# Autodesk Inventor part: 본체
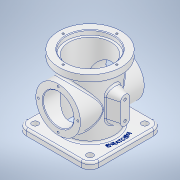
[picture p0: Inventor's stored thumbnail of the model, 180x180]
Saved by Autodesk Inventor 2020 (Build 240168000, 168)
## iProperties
Created: 2021-03
Part Number: 본체
Material: 알루미늄 6061
Document SubType Name: Modeling
Designer: USER
Mass: 869.331 g
Surface Area: 881.277 cm^2
Volume: 321.975 cm^3
Density: 2.7 g/cm^3
Appearance: 알루미늄 - 평지
Author: USER
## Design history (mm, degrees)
sketch "스케치1"
  geometry: L1 (-57, 57)-(57, 57); L2 (57, 57)-(57, -57); L3 (57, -57)-(-57, -57); L4 (-57, -57)-(-57, 57); L5 (-57, 57)-(57, -57); L6 (57, 57)-(-57, -57); 1 further point
  constraints: 12 end point, 2 midpoint, 2 parallel, 2 perpendicular, 1 horizontal
  dimensions: "d0" = 114 distance of L2.end L3.end
extrude "돌출1" new body sketch "스케치1" distance "d1" = 10; taper "d2" = 0 deg
sketch "스케치2"
  geometry: C1 r 38 at (0, 0); 1 further point
  constraints: 1 centre point, 1 coincident
  dimensions: "d3" = 76 diameter of C1
extrude "돌출2" join sketch "스케치2" distance "d4" = 88; taper "d5" = 0 deg
sketch "스케치3"
  geometry: C1 r 49 at (0, 0); 1 further point
  constraints: 1 centre point, 1 coincident
  dimensions: "d6" = 98 diameter of C1
extrude "돌출3" join sketch "스케치3" distance "d7" = 13; taper "d8" = 0 deg
sketch "스케치4"
  geometry: L1 (57, 0)-(-57, 0) reference; C1 r 35 at (0, 54); 1 further point
  constraints: 1 centre point, 1 vertical alignment
  dimensions: "d9" = 70 diameter of C1; "d10" = 54 distance from line of L1 C1.centre
extrude "돌출4" join sketch "스케치4" stored distance "d11" = 100; taper "d12" = 0 deg
sketch "스케치5"
  geometry: C1 r 37 at (0, 0); 1 further point
  constraints: 1 centre point, 1 coincident
  dimensions: "d13" = 74 diameter of C1
extrude "돌출5" cut sketch "스케치5" distance "d14" = 7; taper "d15" = 0 deg
sketch "스케치6"
  geometry: C1 r 33 at (0, 0); 1 further point
  constraints: 1 centre point, 1 coincident
  dimensions: "d16" = 66 diameter of C1
extrude "돌출6" cut sketch "스케치6" extent not by distance; stored distance "d17" = 7; taper "d18" = 0 deg
sketch "스케치8"
  geometry: C1 r 35 at (0, 0) reference; C2 r 24 at (0, 0); 1 further point
  constraints: 1 centre point, 1 coincident
  dimensions: "d19" = 48 diameter of C2
extrude "돌출7" cut sketch "스케치8" extent not by distance; stored distance "d20" = 0; taper "d21" = 0 deg
sketch "스케치9"
  geometry: L1 (24, 22.65)-(24, 50) reference; C1 r 37 at (0, 0) reference; C2 r 49 at (0, 0) reference; 2 further points
  constraints: 1 vertical alignment
  dimensions: "d22" = 42 distance of point (0, 0) point (0, 42)
hole "구멍1" sketch "스케치9" at (0, 42) diameter "d23" = 3.242; stored, may be unused: countersink angle "d27" = 90 deg, drill point angle "d29" = 118 deg; dims "d24" = 6, "d25" = 4, "d26" = 2, "d28" = 8
sketch "스케치10"
  geometry: C1 r 24 at (0, 0) reference; C2 r 35 at (0, 0) reference; 2 further points
  constraints: 1 vertical alignment
  dimensions: "d33" = 31 distance of C1.centre point (0, 31)
hole "구멍2" sketch "스케치10" at (0, 31) diameter "d34" = 3.242; stored, may be unused: countersink angle "d38" = 90 deg, drill point angle "d40" = 118 deg; dims "d35" = 6, "d36" = 4, "d37" = 2, "d39" = 8
node "작업 평면1"
sketch "스케치11"
  geometry: L1 (70, 0)-(41, 0); L2 (70, 7)-(41, 7); L3 (41, -7)-(70, -7); L4 (0, 57)-(0, -57) reference; A1 r 7 centre (70, 0) between (70, -7) and (70, 7); A2 r 7 centre (41, 0) between (41, 7) and (41, -7); 3 further points
  constraints: 8 end point, 4 point on circle, 4 tangent, 2 centre point, 2 midpoint, 1 horizontal, 1 horizontal alignment, 1 parallel
  dimensions: "d45" = 14 distance between parallel lines of L3 L2; "d85" = 41 distance from line of L4 L1.end; "d87" = 29 distance of L1.start L1.end
extrude "돌출8" join sketch "스케치11" stored distance "d48" = 7; taper "d49" = 15 deg
sketch "스케치12"
  geometry: L1 (57, 57)-(-57, 57) reference; L2 (57, -57)-(57, 57) reference; C1 r 5 at (43, 43); 1 further point
  constraints: 1 centre point
  dimensions: "d50" = 10 diameter of C1; "d51" = 14 distance from line of L1 C1.centre; "d52" = 14 distance from line of L2 C1.centre
extrude "돌출9" cut sketch "스케치12" extent not by distance; stored distance "d53" = 0; taper "d54" = 0 deg
fillet "모깎기1" dims "d55" = 14
fillet "모깎기2" dims "d56" = 3
fillet "모깎기3" dims "d57" = 3
fillet "모깎기4" dims "d58" = 3
fillet "모깎기5" dims "d59" = 3
fillet "모깎기6" dims "d60" = 3
fillet "모깎기7" dims "d61" = 3
chamfer "모따기1" distance "d62" = 1; stored, may be unused: second distance "d63" = 2, angle "d64" = 45 deg
chamfer "모따기2" distance "d65" = 1; stored, may be unused: second distance "d66" = 2, angle "d67" = 45 deg
chamfer "모따기3" distance "d68" = 1; stored, may be unused: second distance "d69" = 2, angle "d70" = 45 deg
sketch "스케치13"
  geometry: L1 (-7, 70)-(-7, 41) reference; L2 (7, 41)-(7, 70) reference; A1 r 7 centre (0, 41) between (-7, 41) and (7, 41) reference; A2 r 7 centre (0, 70) between (7, 70) and (-7, 70) reference; 3 further points
  constraints: 2 coincident
hole "구멍3" sketch "스케치13" at (0, 70), (0, 41) diameter "d71" = 4.134; stored, may be unused: countersink angle "d75" = 90 deg, drill point angle "d77" = 118 deg; dims "d72" = 8, "d73" = 4, "d74" = 2, "d76" = 10
sketch "스케치14"
  geometry: C1 r 50 at (0, 0); 1 further point
  constraints: 1 centre point, 1 coincident, 1 other
  dimensions: "d78" = 100 diameter of C1
feature "엠보싱1" sketch "스케치14" dims "d79" = 0.5, "d80" = 0
node "솔리드1"
pattern_circular "원형 패턴1" dims angle "d31" = 360 deg
pattern_circular "원형 패턴2" dims angle "d42" = 360 deg
mirror "미러1"
mirror "미러3"
mirror "미러4"
mirror "미러5"
node "투영된 루프1"
node "투영된 루프2"
node "투영된 루프3"
node "투영된 루프4"
feature "A9D066F2-1C7D-4E18-AEED-F7BC21143FA4" dims "d34" = 3.242, "d35" = 6, "d36" = 4, "d37" = 2, "d38" = 90 deg, "d39" = 8, "d40" = 118 deg
other parameters: "d44" = 55
